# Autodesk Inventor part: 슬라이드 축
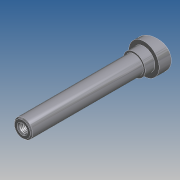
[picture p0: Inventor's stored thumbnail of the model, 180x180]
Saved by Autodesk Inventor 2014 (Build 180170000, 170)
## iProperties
Created: 2012-05
Part Number: 슬라이드 축
Document SubType Name: 모델링
Designer: SeoGD™
Mass: 169.563 g
Surface Area: 67.586 cm^2
Volume: 21.5729 cm^3
Density: 7.86 g/cm^3
Material: 강철, 연강
Appearance: 강철
변환 표준: STEP AP214IS
파일 이름: C:\Users\SeoGD\Desktop\?쒗뿕\異?stp
전처리기: Build: 253, Release: 2010 SP1 - Date: Wed 07/29/2009
전송 단위: 밀리미터
불확실성: 0.01
Author: SeoGD™
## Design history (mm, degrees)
sketch "스케치1"
  geometry: L1 (0, 100)-(7.5, 100); L2 (7.5, 100)-(7.5, 0); L3 (7.5, 0)-(12.5, 0); L4 (12.5, 0)-(12.5, -17); L5 (12.5, -17)-(0, -17); L6 (0, -17)-(0, 100); 1 further point
  constraints: 12 end point, 2 parallel, 2 point on line, 1 perpendicular, 1 vertical
  dimensions: "d0" = 100 distance from line of L1 point (0, 0); "d1" = 15 diameter of L2 L6; "d2" = 25 diameter of L4 L6; "d3" = 17 distance of L3.end L4.end
revolve "회전1" sketch "스케치1" stored, may be unused: angle "d4" = 90 deg
sketch "스케치2"
  geometry: L1 (12.5, 0)-(12.5, -17) reference; L2 (-12.5, -17)-(12.5, -17) reference; L3 (-12.5, 0)-(-12.5, -17) reference; L4 (12.5, -5)-(-12.5, -11.699); L5 (-12.5, 0)-(12.5, 0) reference; 1 further point
  constraints: 2 end point, 2 point on line
  dimensions: "d5" = 75 deg angle of L1 L4; "d6" = 5 distance from line of L4.start L5
extrude "돌출1" cut sketch "스케치2" stored distance "d7" = 10; taper "d8" = 0 deg
chamfer "모따기1" distance "d9" = 1; stored, may be unused: second distance "d10" = 2, angle "d11" = 45 deg
fillet "모깎기1" dims "d12" = 0.5
hole "구멍1" diameter "d15" = 6.647; stored, may be unused: countersink angle "d19" = 90 deg, drill point angle "d21" = 118 deg; dims "d13" = 10, "d14" = 10, "d16" = 17, "d17" = 4, "d18" = 2, "d20" = 20
chamfer "모따기2" distance "d22" = 1; stored, may be unused: second distance "d23" = 2, angle "d24" = 45 deg
sketch "스케치3"
  geometry: C1 r 9 at (0, 0); 1 further point
  constraints: 1 centre point, 1 coincident
  dimensions: "d25" = 18 diameter of C1
extrude "돌출2" join sketch "스케치3" distance "d26" = 8; taper "d27" = 0 deg
node "솔리드1"
node "솔리드 본체"
node "곡면 본체"
node "솔리드2"
